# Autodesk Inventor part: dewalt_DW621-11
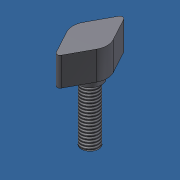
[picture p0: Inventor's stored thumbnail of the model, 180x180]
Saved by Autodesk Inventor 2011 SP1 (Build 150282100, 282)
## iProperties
Created: 2011-02
Part Number: dewalt_DW621-11
Material: 1.0037 St 37-2 / S235JR
Catalog Web Link: www.mittelmeyer.de
Document SubType Name: Modellieren
Designer: TMT
Manufacturer: Standard
Standards Organization: Custom
Density: 1 g/cm^3
Author: TMT
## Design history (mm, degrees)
sketch "Skizze2"
  geometry: C1 r 3 at (0, 0); 1 further point
  constraints: 1 centre point, 1 coincident
  dimensions: "d5" = 6 diameter of C1 (= durchmesser_01)
extrude "Extrusion2" new body sketch "Skizze2" distance "d6" = 20 (= hoehe_01); taper "d7" = 0 deg
sketch "Skizze3"
  geometry: C1 r 3 at (0, 0) reference; C2 r 4 at (0, 0)
  constraints: 1 centre point, 1 coincident
  dimensions: "d8" = 8 diameter of C2
extrude "Extrusion3" join sketch "Skizze3" distance "d9" = 3; taper "d10" = 0 deg
sketch "Skizze4"
  geometry: L1 (-8.4, 0)-(8.4, 0) reference; L2 (0, -16.1)-(0, 16.1) reference; L3 (-5.276, -2.857)-(-0.879, -10.976); L4 (5.276, -2.857)-(0.879, -10.976); L5 (-5.276, 2.857)-(-0.879, 10.976); L6 (5.276, 2.857)-(0.879, 10.976); C1 r 4 at (0, 0) reference; A1 r 6 centre (0, 0) between (-5.276, -2.857) and (5.276, -2.857); A2 r 1 centre (0, -10.5) between (-0.879, -10.976) and (0.879, -10.976); A3 r 1 centre (0, 10.5) between (-0.879, 10.976) and (0.879, 10.976)
  constraints: 8 end point, 8 point on circle, 8 tangent, 3 centre point, 2 point on line, 1 coincident, 1 other
  dimensions: "d11" = 12 diameter of A1; "d12" = 2 diameter of A2; "d13" = 21 distance of A3.centre A2.centre
extrude "Extrusion4" join sketch "Skizze4" distance "d14" = 10; taper "d15" = 0 deg
feature "Gewinde1" dims "d16" = 10, "d17" = 0
node "Volumenkörper1"
node "Volumenkörpern"
node "Oberflächenkörpern"
other parameters: "durchmesser_01" = 6 [user parameter; used in 1 equation term], "hoehe_01" = 20 [user parameter; used in 1 equation term]
